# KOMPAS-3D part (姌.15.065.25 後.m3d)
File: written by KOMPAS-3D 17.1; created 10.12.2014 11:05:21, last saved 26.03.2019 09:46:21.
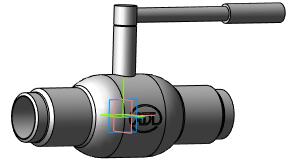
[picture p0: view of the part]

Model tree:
1. Операция без истории:4  (labels: Сталь 20  ГОСТ 1050-88)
